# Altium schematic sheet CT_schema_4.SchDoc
size 165 x 142 mm
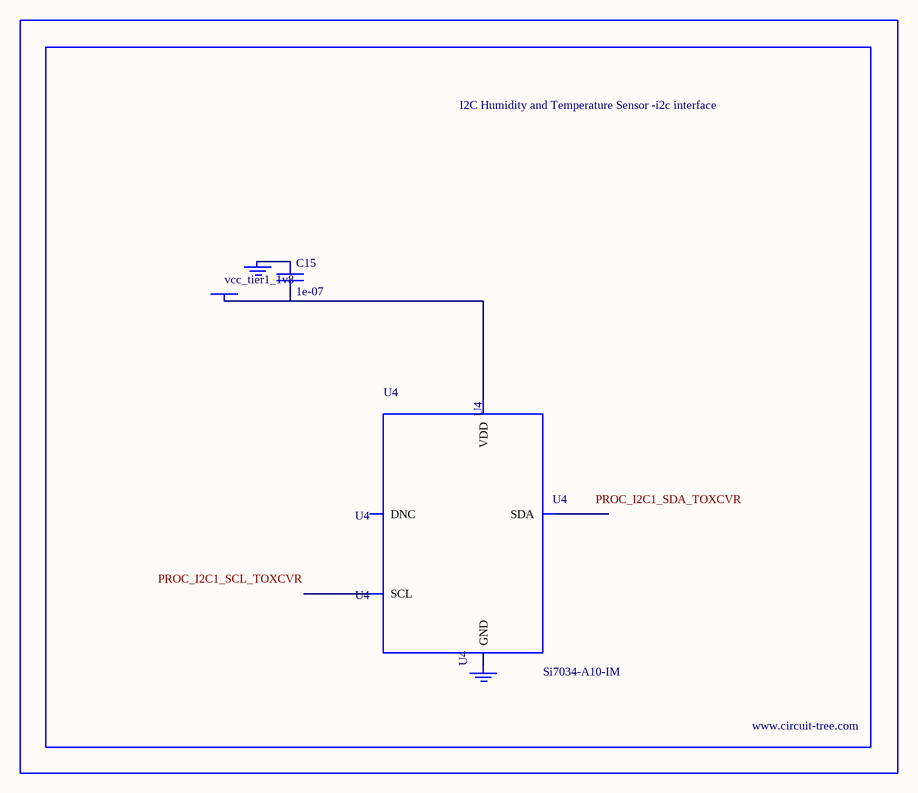
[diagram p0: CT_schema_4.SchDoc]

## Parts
BORDER3  (no value)
C15  1e-07  [C0402]
GND_INSTANCE_3_0  (no value)
GND_INSTANCE_3_1  (no value)
POWER_INSTANCE_3_0  vcc_tier1_1v8
U4  Si7034-A10-IM  [SI7034-A10-IM]

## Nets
NetC15_1: C15.1 GND_INSTANCE_3_0.0(GND)
NetC15_2: C15.2 POWER_INSTANCE_3_0.0(PWR) U4.1(VDD)
NetGND_INSTANCE_3_1_0: GND_INSTANCE_3_1.0(GND) U4.5(GND)

Not connected (* = marked no-connect by the designer): U4 2(SCL) 3(DNC) 4(SDA)

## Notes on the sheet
- Labels drawn without touching a wire or pin: PROC_I2C1_SCL_TOXCVR, PROC_I2C1_SDA_TOXCVR

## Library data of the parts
BORDER3 = BORDER_PAGE3
C15 = C0402C104K3RACTU
GND_INSTANCE_3_0 GND_INSTANCE_3_1 = GND
POWER_INSTANCE_3_0 = PWR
